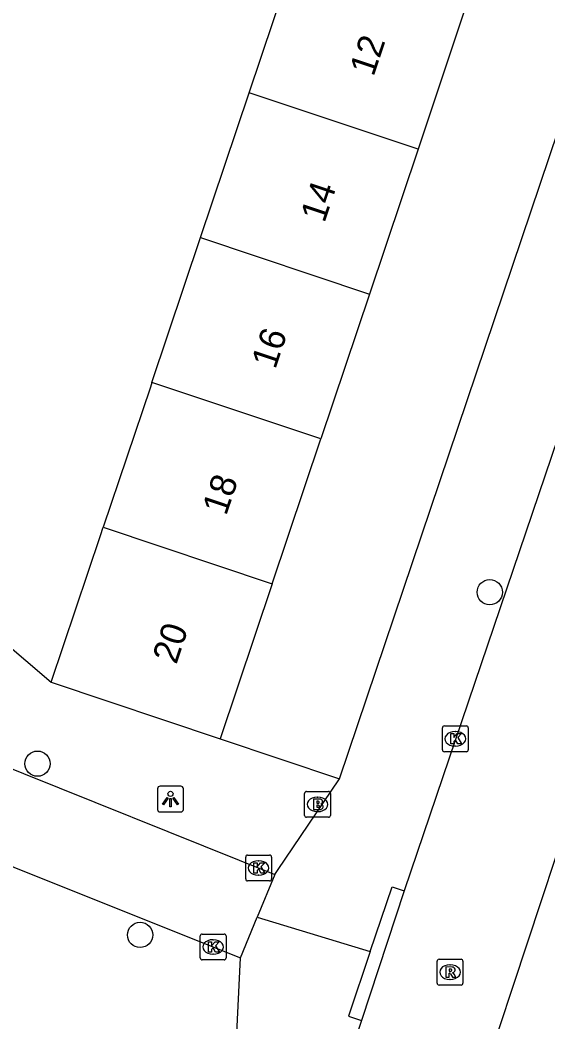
# Model space of a CAD drawing. Extents: x 162532 to 163264, y 381233 to 382042.
# Drawn here: x 163205.75 to 163226.19, y 381572.14 to 381610.96 of the extents above; entities that cross this region are included whole.
import ezdxf

# ---------------------------------------------------------------- set-up
doc = ezdxf.new("R2010")
doc.units = 0
for name, color, linetype in [('IMGEO_Boom', 7, 'Continuous'), ('IMGEO_Brandkraan', 7, 'Continuous'), ('IMGEO_Kolk', 7, 'Continuous'), ('IMGEO_Lichtpunt', 7, 'Continuous'), ('IMGEO_Pand', 7, 'Continuous'), ('IMGEO_Pand_nummerreeks', 7, 'Continuous'), ('IMGEO_Rijbaan_lokaal_open', 7, 'Continuous'), ('IMGEO_Rioolput', 7, 'Continuous'), ('IMGEO_Voetpad_open', 7, 'Continuous')]:
    doc.layers.add(name, color=color, linetype=linetype)

msp = doc.modelspace()

# ---------------------------------------------------------------- linework, layer by layer
at = {"layer": 'IMGEO_Boom'}
for centre in [(163223.937, 381588.789), (163206.43, 381582.145), (163210.401, 381575.509)]:
    msp.add_circle(centre, 0.489, dxfattribs=at)
at = {"layer": 'IMGEO_Brandkraan'}
for p, q in [((163216.769, 381580.143), (163216.769, 381580.995)), ((163216.844, 381581.069), (163217.696, 381581.069)), ((163217.77, 381580.995), (163217.77, 381580.143)), ((163217.257, 381580.849), (163217.282, 381580.849)), ((163217.28, 381580.289), (163217.255, 381580.289)), ((163217.696, 381580.069), (163216.844, 381580.069))]:
    msp.add_line(p, q, dxfattribs=at)
for points in [[(163216.769, 381580.143), (163216.769, 381580.995)], [(163216.844, 381581.069), (163217.696, 381581.069)], [(163217.77, 381580.995), (163217.77, 381580.143)], [(163217.117, 381580.769), (163217.117, 381580.369), (163217.33, 381580.369)], [(163217.348, 381580.769), (163217.117, 381580.769)], [(163217.296, 381580.688), (163217.242, 381580.688), (163217.242, 381580.612)], [(163217.242, 381580.612), (163217.295, 381580.612)], [(163217.304, 381580.536), (163217.242, 381580.536), (163217.242, 381580.455)], [(163217.242, 381580.455), (163217.304, 381580.455)], [(163217.696, 381580.069), (163216.844, 381580.069)]]:
    msp.add_lwpolyline(points, dxfattribs=at)
for centre, radius, start, end in [((163216.846, 381580.993), 0.0765, 91.552, 178.448), ((163216.846, 381580.993), 0.0765, 91.552, 178.448), ((163217.694, 381580.993), 0.0765, 1.552, 88.448), ((163217.694, 381580.993), 0.0765, 1.552, 88.448), ((163217.297, 381580.65), 0.0379, 267.8285, 90.9355), ((163217.352, 381580.624), 0.145, 59.4692, 91.5367), ((163217.377, 381580.671), 0.0922, 285.5137, 58.1501), ((163217.382, 381580.479), 0.105, 301.3115, 78.989), ((163217.305, 381580.495), 0.0404, 269.8759, 90.5077), ((163217.336, 381580.62), 0.251, 268.6676, 293.5347), ((163216.846, 381580.145), 0.0765, 181.552, 268.448), ((163216.846, 381580.145), 0.0765, 181.552, 268.448), ((163217.694, 381580.145), 0.0765, 271.552, 358.448), ((163217.694, 381580.145), 0.0765, 271.552, 358.448)]:
    msp.add_arc(centre, radius, start, end, dxfattribs=at)
for centre, major_axis, ratio, start_param, end_param in [((163217.256, 381580.569), (-0.387, 0.002), 0.722429, 4.712389, 7.853982), ((163217.281, 381580.569), (-0.39, 0.002), 0.717154, 1.570796, 4.712389)]:
    msp.add_ellipse(centre, major_axis=major_axis, ratio=ratio, start_param=start_param, end_param=end_param, dxfattribs=at)
at = {"layer": 'IMGEO_Kolk'}
for p, q in [((163222.104, 381582.684), (163222.104, 381583.536)), ((163222.179, 381583.61), (163223.031, 381583.61)), ((163222.592, 381583.39), (163222.617, 381583.39)), ((163223.105, 381583.536), (163223.105, 381582.684)), ((163223.031, 381582.61), (163222.179, 381582.61)), ((163222.615, 381582.83), (163222.59, 381582.83)), ((163214.488, 381577.677), (163214.488, 381578.529)), ((163214.563, 381578.603), (163215.415, 381578.603)), ((163214.976, 381578.383), (163215.001, 381578.383)), ((163215.489, 381578.529), (163215.489, 381577.677)), ((163215.415, 381577.603), (163214.563, 381577.603)), ((163214.999, 381577.823), (163214.974, 381577.823)), ((163212.802, 381575.543), (163213.654, 381575.543)), ((163212.727, 381574.617), (163212.727, 381575.469)), ((163213.215, 381575.323), (163213.24, 381575.323)), ((163213.728, 381575.469), (163213.728, 381574.617)), ((163213.238, 381574.763), (163213.213, 381574.763)), ((163213.654, 381574.543), (163212.802, 381574.543))]:
    msp.add_line(p, q, dxfattribs=at)
for points in [[(163222.104, 381582.684), (163222.104, 381583.536)], [(163222.179, 381583.61), (163223.031, 381583.61)], [(163222.425, 381583.31), (163222.548, 381583.31), (163222.548, 381583.159), (163222.678, 381583.31), (163222.842, 381583.31), (163222.696, 381583.159), (163222.849, 381582.91), (163222.697, 381582.91), (163222.612, 381583.074), (163222.548, 381583.007), (163222.548, 381582.91), (163222.425, 381582.91), (163222.425, 381583.31)], [(163223.105, 381583.536), (163223.105, 381582.684)], [(163223.031, 381582.61), (163222.179, 381582.61)], [(163214.488, 381577.677), (163214.488, 381578.529)], [(163214.563, 381578.603), (163215.415, 381578.603)], [(163214.809, 381578.303), (163214.932, 381578.303), (163214.932, 381578.152), (163215.062, 381578.303), (163215.226, 381578.303), (163215.08, 381578.152), (163215.233, 381577.903), (163215.081, 381577.903), (163214.996, 381578.067), (163214.932, 381578), (163214.932, 381577.903), (163214.809, 381577.903), (163214.809, 381578.303)], [(163215.489, 381578.529), (163215.489, 381577.677)], [(163215.415, 381577.603), (163214.563, 381577.603)], [(163212.802, 381575.543), (163213.654, 381575.543)], [(163212.727, 381574.617), (163212.727, 381575.469)], [(163213.048, 381575.243), (163213.171, 381575.243), (163213.171, 381575.092), (163213.301, 381575.243), (163213.465, 381575.243), (163213.319, 381575.092), (163213.472, 381574.843), (163213.32, 381574.843), (163213.235, 381575.007), (163213.171, 381574.94), (163213.171, 381574.843), (163213.048, 381574.843), (163213.048, 381575.243)], [(163213.728, 381575.469), (163213.728, 381574.617)], [(163213.654, 381574.543), (163212.802, 381574.543)]]:
    msp.add_lwpolyline(points, dxfattribs=at)
for centre, start, end in [((163222.181, 381583.534), 91.552, 178.448), ((163222.181, 381583.534), 91.552, 178.448), ((163223.029, 381583.534), 1.552, 88.448), ((163223.029, 381583.534), 1.552, 88.448), ((163222.181, 381582.686), 181.552, 268.448), ((163222.181, 381582.686), 181.552, 268.448), ((163223.029, 381582.686), 271.552, 358.448), ((163223.029, 381582.686), 271.552, 358.448), ((163214.565, 381578.527), 91.552, 178.448), ((163214.565, 381578.527), 91.552, 178.448), ((163215.413, 381578.527), 1.552, 88.448), ((163215.413, 381578.527), 1.552, 88.448), ((163214.565, 381577.679), 181.552, 268.448), ((163214.565, 381577.679), 181.552, 268.448), ((163215.413, 381577.679), 271.552, 358.448), ((163215.413, 381577.679), 271.552, 358.448), ((163212.804, 381575.467), 91.552, 178.448), ((163212.804, 381575.467), 91.552, 178.448), ((163213.652, 381575.467), 1.552, 88.448), ((163213.652, 381575.467), 1.552, 88.448), ((163212.804, 381574.619), 181.552, 268.448), ((163212.804, 381574.619), 181.552, 268.448), ((163213.652, 381574.619), 271.552, 358.448), ((163213.652, 381574.619), 271.552, 358.448)]:
    msp.add_arc(centre, 0.0765, start, end, dxfattribs=at)
for centre, major_axis, ratio, start_param, end_param in [((163222.591, 381583.11), (-0.387, 0.002), 0.722429, 4.712389, 7.853982), ((163222.616, 381583.11), (-0.39, 0.002), 0.717154, 1.570796, 4.712389), ((163214.975, 381578.103), (-0.387, 0.002), 0.722429, 4.712389, 7.853982), ((163215, 381578.103), (-0.39, 0.002), 0.717154, 1.570796, 4.712389), ((163213.214, 381575.043), (-0.387, 0.002), 0.722429, 4.712389, 7.853982), ((163213.239, 381575.043), (-0.39, 0.002), 0.717154, 1.570796, 4.712389)]:
    msp.add_ellipse(centre, major_axis=major_axis, ratio=ratio, start_param=start_param, end_param=end_param, dxfattribs=at)
at = {"layer": 'IMGEO_Lichtpunt'}
for p, q in [((163211.079, 381581.177), (163211.079, 381580.37)), ((163211.079, 381581.177), (163211.079, 381580.37)), ((163211.981, 381581.272), (163211.173, 381581.272)), ((163211.981, 381581.272), (163211.173, 381581.272)), ((163212.075, 381580.37), (163212.075, 381581.177)), ((163212.075, 381580.37), (163212.075, 381581.177)), ((163211.173, 381580.276), (163211.981, 381580.276)), ((163211.173, 381580.276), (163211.981, 381580.276))]:
    msp.add_line(p, q, dxfattribs=at)
for points in [[(163211.453, 381580.841), (163211.492, 381580.813), (163211.304, 381580.551), (163211.266, 381580.578), (163211.453, 381580.841)], [(163211.555, 381580.793), (163211.602, 381580.793), (163211.602, 381580.471), (163211.555, 381580.471), (163211.555, 381580.793)], [(163211.665, 381580.813), (163211.703, 381580.84), (163211.89, 381580.578), (163211.851, 381580.55), (163211.665, 381580.813)]]:
    msp.add_lwpolyline(points, dxfattribs=at)
msp.add_circle((163211.578, 381580.975), 0.0994, dxfattribs=at)
for centre, start, end in [((163211.173, 381581.177), 90, 180), ((163211.173, 381581.177), 90, 180), ((163211.981, 381581.177), 0, 90), ((163211.981, 381581.177), 0, 90), ((163211.173, 381580.37), 180, 270), ((163211.173, 381580.37), 180, 270), ((163211.981, 381580.37), 270, 0), ((163211.981, 381580.37), 270, 360)]:
    msp.add_arc(centre, 0.0946, start, end, dxfattribs=at)
at = {"layer": 'IMGEO_Pand'}
for points in [[(163214.627, 381608.145), (163216.511, 381613.759)], [(163223.042, 381611.57), (163221.161, 381605.956)], [(163212.744, 381602.533), (163214.627, 381608.145)], [(163221.161, 381605.956), (163214.627, 381608.145)], [(163221.161, 381605.956), (163219.279, 381600.343)], [(163210.861, 381596.921), (163212.744, 381602.533)], [(163212.744, 381602.533), (163219.279, 381600.343)], [(163219.279, 381600.343), (163217.398, 381594.73)], [(163210.861, 381596.921), (163210.801, 381596.741), (163208.977, 381591.308)], [(163217.398, 381594.73), (163210.861, 381596.921)], [(163215.517, 381589.117), (163217.398, 381594.73)], [(163206.962, 381585.303), (163208.868, 381590.983), (163208.977, 381591.308)], [(163208.977, 381591.308), (163215.517, 381589.117)], [(163215.517, 381589.117), (163213.504, 381583.11)], [(163206.962, 381585.303), (163213.504, 381583.11)]]:
    msp.add_lwpolyline(points, dxfattribs=at)
at = {"layer": 'IMGEO_Rijbaan_lokaal_open'}
for points in [[(163239.465, 381633.208), (163239.289, 381632.743), (163235.731, 381622.012), (163230.538, 381606.464), (163220.627, 381577.214)], [(163199.049, 381582.352), (163199.687, 381581.799), (163202.492, 381579.513), (163202.783, 381579.345), (163204.21, 381578.732), (163205.538, 381578.122), (163214.293, 381574.618)], [(163204.493, 381582.322), (163215.616, 381577.85)], [(163222.115, 381565.284), (163227.041, 381580.166)], [(163215.616, 381577.85), (163214.938, 381576.194)], [(163220.627, 381577.214), (163218.97, 381572.196)], [(163214.293, 381574.618), (163214.938, 381576.194)], [(163218.97, 381572.196), (163199.194, 381512.302)]]:
    msp.add_lwpolyline(points, dxfattribs=at)
at = {"layer": 'IMGEO_Rioolput'}
for p, q in [((163221.899, 381573.642), (163221.899, 381574.494)), ((163221.974, 381574.568), (163222.826, 381574.568)), ((163222.9, 381574.494), (163222.9, 381573.642)), ((163222.387, 381574.348), (163222.412, 381574.348)), ((163222.41, 381573.788), (163222.385, 381573.788)), ((163222.826, 381573.568), (163221.974, 381573.568))]:
    msp.add_line(p, q, dxfattribs=at)
for points in [[(163221.899, 381573.642), (163221.899, 381574.494)], [(163221.974, 381574.568), (163222.826, 381574.568)], [(163222.9, 381574.494), (163222.9, 381573.642)], [(163222.488, 381574.266), (163222.236, 381574.268), (163222.236, 381573.868)], [(163222.236, 381573.868), (163222.36, 381573.868), (163222.36, 381574.03), (163222.371, 381574.03)], [(163222.414, 381574.187), (163222.36, 381574.187), (163222.36, 381574.106)], [(163222.36, 381574.106), (163222.412, 381574.106)], [(163222.418, 381574.001), (163222.489, 381573.868), (163222.629, 381573.868), (163222.564, 381573.994)], [(163222.826, 381573.568), (163221.974, 381573.568)]]:
    msp.add_lwpolyline(points, dxfattribs=at)
for centre, radius, start, end in [((163221.976, 381574.492), 0.0765, 91.552, 178.448), ((163221.976, 381574.492), 0.0765, 91.552, 178.448), ((163222.824, 381574.492), 0.0765, 1.552, 88.448), ((163222.824, 381574.492), 0.0765, 1.552, 88.448), ((163222.37, 381573.977), 0.0533, 26.0293, 88.6989), ((163222.396, 381574.295), 0.19, 274.7715, 282.9687), ((163222.42, 381574.091), 0.0964, 77.0061, 93.1865), ((163222.434, 381574.148), 0.0378, 276.6634, 79.6772), ((163222.487, 381574.156), 0.109, 350.3612, 89.416), ((163222.485, 381574.156), 0.112, 277.5842, 350.9817), ((163222.469, 381573.941), 0.108, 29.5134, 73.7905), ((163221.976, 381573.644), 0.0765, 181.552, 268.448), ((163221.976, 381573.644), 0.0765, 181.552, 268.448), ((163222.824, 381573.644), 0.0765, 271.552, 358.448), ((163222.824, 381573.644), 0.0765, 271.552, 358.448)]:
    msp.add_arc(centre, radius, start, end, dxfattribs=at)
for centre, major_axis, ratio, start_param, end_param in [((163222.386, 381574.068), (-0.387, 0.002), 0.722429, 4.712389, 7.853982), ((163222.411, 381574.068), (-0.39, 0.002), 0.717154, 1.570796, 4.712389)]:
    msp.add_ellipse(centre, major_axis=major_axis, ratio=ratio, start_param=start_param, end_param=end_param, dxfattribs=at)
at = {"layer": 'IMGEO_Voetpad_open'}
for points in [[(163218.125, 381581.561), (163236.83, 381637.078), (163237.882, 381640.331)], [(163194.728, 381595.768), (163206.962, 381585.303)], [(163213.504, 381583.11), (163218.125, 381581.561)], [(163215.616, 381577.85), (163215.721, 381578.005), (163218.125, 381581.561)], [(163219.313, 381574.869), (163220.154, 381577.373), (163220.627, 381577.214)], [(163214.938, 381576.194), (163219.313, 381574.869)], [(163219.313, 381574.869), (163218.472, 381572.364), (163218.97, 381572.196)], [(163214.034, 381569.315), (163214.293, 381574.618)]]:
    msp.add_lwpolyline(points, dxfattribs=at)

# ---------------------------------------------------------------- texts
at = {"layer": 'IMGEO_Pand_nummerreeks'}
for s, rotation, p in [('12', 71.4721, (163219.435, 381608.74)), ('14', 71.4721, (163217.535, 381603.07)), ('16', 71.4721, (163215.634, 381597.397)), ('18', 71.4708, (163213.733, 381591.726)), ('20', 71.4708, (163211.803, 381585.966))]:
    msp.add_text(s, height=1, rotation=rotation, dxfattribs=at).set_placement(p)

doc.saveas('drawing.dxf')
